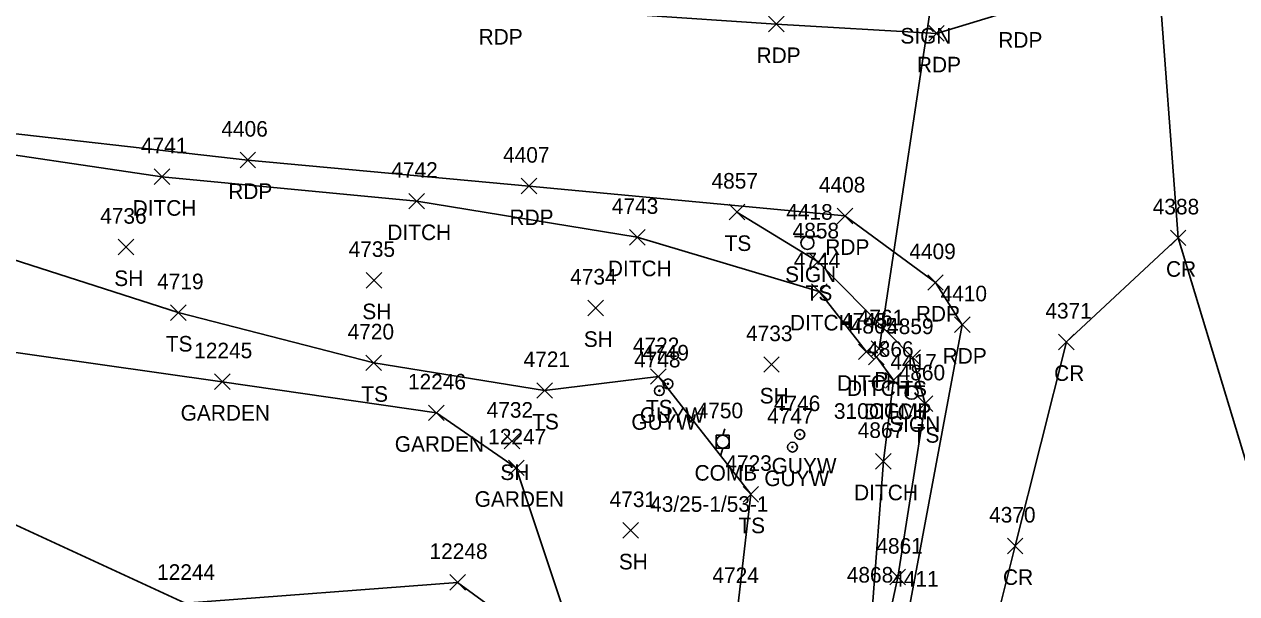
# Model space of a CAD drawing. Extents: x 1482574 to 1485769, y 580696 to 595649.
# Drawn here: x 1483403.4 to 1483558.8, y 583592.2 to 583665.3 of the extents above; entities that cross this region are included whole.
import ezdxf

# ---------------------------------------------------------------- set-up
doc = ezdxf.new("R2010")
doc.units = 0
for name, color, linetype in [('D_A', 7, 'Continuous'), ('D_C', 7, 'Continuous'), ('D_I', 7, 'Continuous'), ('D_TIC', 7, 'Continuous'), ('DCP', 7, 'Continuous'), ('DD', 7, 'Continuous'), ('L_A', 7, 'Continuous'), ('L_I', 7, 'Continuous'), ('L_TIC', 7, 'Continuous'), ('LAPB', 7, 'Continuous'), ('LELB', 7, 'Continuous'), ('P_A', 7, 'Continuous'), ('P_I', 7, 'Continuous'), ('P_TIC', 7, 'Continuous'), ('PET', 7, 'Continuous'), ('PRC', 7, 'Continuous'), ('S_A', 7, 'Continuous'), ('S_I', 7, 'Continuous'), ('SSGN', 7, 'Continuous'), ('U_A', 7, 'Continuous'), ('U_C', 7, 'Continuous'), ('U_I', 7, 'Continuous'), ('UP', 7, 'Continuous'), ('UPGW', 7, 'Continuous')]:
    doc.layers.add(name, color=color, linetype=linetype)

msp = doc.modelspace()

# ---------------------------------------------------------------- linework, layer by layer
at = {"layer": 'D_TIC'}
for points in [[(1483420.05, 583644.72), (1483422.05, 583646.72)], [(1483422.05, 583644.72), (1483420.05, 583646.72)], [(1483452.7, 583641.59), (1483454.7, 583643.59)], [(1483454.7, 583641.59), (1483452.7, 583643.59)], [(1483480.96, 583636.96), (1483482.96, 583638.96)], [(1483482.96, 583636.96), (1483480.96, 583638.96)], [(1483504.28, 583630), (1483506.28, 583632)], [(1483506.28, 583630), (1483504.28, 583632)], [(1483511.95, 583622.66), (1483513.95, 583624.66)], [(1483513.95, 583622.66), (1483511.95, 583624.66)], [(1483510.33, 583622.26), (1483512.33, 583624.26)], [(1483512.33, 583622.26), (1483510.33, 583624.26)], [(1483511.61, 583621.6), (1483513.61, 583623.6)], [(1483513.61, 583621.6), (1483511.61, 583623.6)], [(1483513.79, 583618.61), (1483515.79, 583620.61)], [(1483515.79, 583618.61), (1483513.79, 583620.61)], [(1483512.51, 583608.21), (1483514.51, 583610.21)], [(1483514.51, 583608.21), (1483512.51, 583610.21)]]:
    msp.add_lwpolyline(points, dxfattribs=at)
at = {"layer": 'DCP'}
msp.add_lwpolyline([(1483520.62, 583674.51), (1483512.95, 583623.66)], dxfattribs=at)
at = {"layer": 'DD'}
for points in [[(1483363.65, 583647.41), (1483379.49, 583650.79), (1483392.76, 583649.91), (1483421.05, 583645.72), (1483453.7, 583642.59), (1483481.96, 583637.96), (1483505.28, 583631), (1483511.33, 583623.26)], [(1483512.61, 583622.6), (1483514.79, 583619.61), (1483513.51, 583609.21), (1483512.11, 583590.65)]]:
    msp.add_lwpolyline(points, dxfattribs=at)
at = {"layer": 'L_TIC'}
for points in [[(1483493.74, 583640.2), (1483495.74, 583642.2)], [(1483495.74, 583640.2), (1483493.74, 583642.2)], [(1483415.45, 583635.7), (1483417.45, 583637.7)], [(1483417.45, 583635.7), (1483415.45, 583637.7)], [(1483504.13, 583633.81), (1483506.13, 583635.81)], [(1483506.13, 583633.81), (1483504.13, 583635.81)], [(1483447.23, 583631.44), (1483449.23, 583633.43)], [(1483449.23, 583631.44), (1483447.23, 583633.43)], [(1483422.13, 583627.29), (1483424.13, 583629.29)], [(1483424.13, 583627.29), (1483422.13, 583629.29)], [(1483475.62, 583627.89), (1483477.62, 583629.89)], [(1483477.62, 583627.89), (1483475.62, 583629.89)], [(1483447.19, 583620.85), (1483449.19, 583622.85)], [(1483449.19, 583620.85), (1483447.19, 583622.85)], [(1483516.25, 583621.53), (1483518.25, 583623.53)], [(1483518.25, 583621.53), (1483516.25, 583623.53)], [(1483498.16, 583620.63), (1483500.16, 583622.63)], [(1483500.16, 583620.63), (1483498.16, 583622.63)], [(1483427.78, 583618.43), (1483429.78, 583620.43)], [(1483429.78, 583618.43), (1483427.78, 583620.43)], [(1483483.66, 583619.09), (1483485.66, 583621.09)], [(1483485.66, 583619.09), (1483483.66, 583621.09)], [(1483469.08, 583617.3), (1483471.08, 583619.3)], [(1483471.08, 583617.3), (1483469.08, 583619.3)], [(1483517.85, 583615.6), (1483519.85, 583617.6)], [(1483519.85, 583615.6), (1483517.85, 583617.6)], [(1483455.21, 583614.43), (1483457.21, 583616.43)], [(1483457.21, 583614.43), (1483455.21, 583616.43)], [(1483464.92, 583610.81), (1483466.92, 583612.8)], [(1483466.92, 583610.81), (1483464.92, 583612.8)], [(1483465.45, 583607.37), (1483467.45, 583609.37)], [(1483467.45, 583607.37), (1483465.45, 583609.37)], [(1483495.51, 583603.98), (1483497.51, 583605.98)], [(1483497.51, 583603.98), (1483495.51, 583605.98)], [(1483480.11, 583599.35), (1483482.11, 583601.34)], [(1483482.11, 583599.35), (1483480.11, 583601.34)], [(1483514.34, 583593.36), (1483516.34, 583595.36)], [(1483516.34, 583593.36), (1483514.34, 583595.36)], [(1483457.93, 583592.68), (1483459.93, 583594.68)], [(1483459.93, 583592.68), (1483457.93, 583594.68)]]:
    msp.add_lwpolyline(points, dxfattribs=at)
at = {"layer": 'LAPB'}
msp.add_lwpolyline([(1483282.4, 583578.39), (1483283.47, 583588.15), (1483286.7, 583605.78), (1483289.8, 583624.64), (1483321.44, 583622.2), (1483367, 583615.82), (1483388.72, 583625.08), (1483428.78, 583619.43), (1483456.21, 583615.43), (1483466.45, 583608.37), (1483475.33, 583581.68)], dxfattribs=at)
at = {"layer": 'LELB'}
for points in [[(1482693.36, 583744.09), (1482726.2, 583730.25), (1482752.08, 583734.83), (1482783.99, 583736.05), (1482832.7, 583724.8), (1482871.74, 583713.41), (1482927.54, 583691.3), (1482963.28, 583665.68), (1482985.39, 583638.72), (1483019.29, 583636.93), (1483075.47, 583645.23), (1483111.09, 583648.77), (1483168.41, 583642.8), (1483210.26, 583617.48), (1483249.85, 583606.69), (1483286.7, 583605.78), (1483319.69, 583604.62), (1483362.38, 583602.89), (1483387.32, 583607.94), (1483424.01, 583591), (1483458.93, 583593.68), (1483475.33, 583581.68)], [(1483376.2, 583646.83), (1483397.16, 583636.64), (1483423.13, 583628.29), (1483448.19, 583621.85), (1483470.08, 583618.3), (1483484.66, 583620.09), (1483496.51, 583604.98), (1483494.85, 583590.59), (1483486.7, 583571.99), (1483482.44, 583553.2), (1483482.84, 583528.89)], [(1483494.74, 583641.2), (1483505.13, 583634.81), (1483517.25, 583622.53), (1483518.85, 583616.6), (1483515.34, 583594.36)], [(1483510.38, 583571.49), (1483515.34, 583594.36)]]:
    msp.add_lwpolyline(points, dxfattribs=at)
at = {"layer": 'P_TIC'}
for points in [[(1483498.77, 583664.31), (1483500.77, 583666.31)], [(1483500.77, 583664.31), (1483498.77, 583666.31)], [(1483519.31, 583663.11), (1483521.31, 583665.11)], [(1483521.31, 583663.11), (1483519.31, 583665.11)], [(1483431.05, 583646.87), (1483433.05, 583648.87)], [(1483433.05, 583646.87), (1483431.05, 583648.87)], [(1483467.1, 583643.53), (1483469.1, 583645.52)], [(1483469.1, 583643.53), (1483467.1, 583645.52)], [(1483507.58, 583639.7), (1483509.58, 583641.7)], [(1483509.58, 583639.7), (1483507.58, 583641.7)], [(1483550.28, 583636.89), (1483552.28, 583638.89)], [(1483552.28, 583636.89), (1483550.28, 583638.89)], [(1483519.18, 583631.15), (1483521.18, 583633.15)], [(1483521.18, 583631.15), (1483519.18, 583633.15)], [(1483522.61, 583625.74), (1483524.61, 583627.74)], [(1483524.61, 583625.74), (1483522.61, 583627.74)], [(1483535.95, 583623.53), (1483537.95, 583625.53)], [(1483537.95, 583623.53), (1483535.95, 583625.53)], [(1483529.39, 583597.35), (1483531.39, 583599.35)], [(1483531.39, 583597.35), (1483529.39, 583599.35)]]:
    msp.add_lwpolyline(points, dxfattribs=at)
at = {"layer": 'PET'}
for points in [[(1483366.75, 583680.51), (1483398.39, 583674.83), (1483429.12, 583670.98), (1483464.15, 583667.68), (1483499.77, 583665.31), (1483520.31, 583664.11), (1483530.74, 583667.28), (1483533.99, 583674.02), (1483537.43, 583706.71), (1483542.63, 583742.49), (1483548.55, 583777.29), (1483553.62, 583807.06)], [(1483359.39, 583657.75), (1483395.14, 583652.04), (1483432.05, 583647.87), (1483468.1, 583644.53), (1483508.57, 583640.7), (1483520.18, 583632.15), (1483523.61, 583626.74), (1483516.76, 583590.13)]]:
    msp.add_lwpolyline(points, dxfattribs=at)
at = {"layer": 'PRC'}
for points in [[(1483618.73, 583521.67), (1483605.12, 583536.57), (1483580.09, 583569.69), (1483562.2, 583601.73), (1483551.28, 583637.89), (1483548.66, 583672.74), (1483550.4, 583708.14), (1483555.34, 583744.78), (1483561.11, 583779.91), (1483565.84, 583808.31), (1483572.09, 583842.87), (1483580.82, 583892.49), (1483589.4, 583942.82)], [(1483551.28, 583637.89), (1483536.95, 583624.53)], [(1483530.39, 583598.35), (1483536.95, 583624.53)], [(1483522.82, 583568.08), (1483530.39, 583598.35)]]:
    msp.add_lwpolyline(points, dxfattribs=at)
at = {"layer": 'SSGN'}
for p, q in [((1483502.12, 583638.06), (1483505.46, 583638.06)), ((1483503.77, 583637.23), (1483503.77, 583637.23)), ((1483515.46, 583618.84), (1483518.8, 583618.84)), ((1483517.11, 583618), (1483517.11, 583618))]:
    msp.add_line(p, q, dxfattribs=at)
for centre in [(1483503.77, 583637.23), (1483517.11, 583618)]:
    msp.add_circle(centre, 0.833, dxfattribs=at)
at = {"layer": 'UP'}
for p, q in [((1483492.09, 583610.89), (1483492.09, 583612.56)), ((1483492.09, 583612.56), (1483493.75, 583612.56)), ((1483493.17, 583613.39), (1483492.92, 583612.56)), ((1483493.75, 583612.56), (1483493.75, 583610.89)), ((1483493.75, 583610.89), (1483492.09, 583610.89)), ((1483492.67, 583610.06), (1483492.92, 583610.89)), ((1483492.92, 583611.73), (1483492.92, 583611.73))]:
    msp.add_line(p, q, dxfattribs=at)
msp.add_circle((1483492.92, 583611.73), 0.833, dxfattribs=at)
at = {"layer": 'UPGW'}
for centre, radius in [((1483485.9, 583619.15), 0.625), ((1483484.8, 583618.26), 0.625), ((1483484.8, 583618.26), 0.0833), ((1483485.9, 583619.15), 0.0833), ((1483502.79, 583612.65), 0.625), ((1483502.79, 583612.65), 0.0833), ((1483501.85, 583611.03), 0.625), ((1483501.85, 583611.03), 0.0833)]:
    msp.add_circle(centre, radius, dxfattribs=at)

# ---------------------------------------------------------------- texts
at = {"layer": 'D_A'}
for s, p in [('DITCH', (1483417.29, 583640.72)), ('DITCH', (1483449.94, 583637.59)), ('DITCH', (1483478.19, 583632.96)), ('DITCH', (1483501.52, 583626)), ('DITCH', (1483507.57, 583618.26)), ('P', (1483512.33, 583618.66)), ('DITCH', (1483508.85, 583617.6)), ('DITCH', (1483511.02, 583614.61)), ('DITCH', (1483509.75, 583604.21))]:
    msp.add_text(s, height=2, dxfattribs=at).set_placement(p)
at = {"layer": 'D_C'}
msp.add_text('310CGMP', height=2, dxfattribs=at).set_placement((1483507.16, 583614.66))
at = {"layer": 'D_I'}
for s, p in [('4741', (1483418.36, 583648.72)), ('4742', (1483450.44, 583645.59)), ('4743', (1483478.7, 583640.96)), ('4744', (1483502.02, 583634)), ('4745', (1483508.07, 583626.26)), ('4865', (1483509.31, 583625.6)), ('4761', (1483510.21, 583626.66)), ('4866', (1483511.42, 583622.61)), ('4867', (1483510.21, 583612.21)), ('4868', (1483508.81, 583593.65))]:
    msp.add_text(s, height=2, dxfattribs=at).set_placement(p)
at = {"layer": 'L_A'}
for s, p in [('TS', (1483493.15, 583636.2)), ('SH', (1483414.93, 583631.7)), ('TS', (1483503.54, 583629.81)), ('SH', (1483446.72, 583627.44)), ('SH', (1483475.11, 583623.89)), ('TS', (1483421.54, 583623.29)), ('TS', (1483446.6, 583616.85)), ('SH', (1483497.65, 583616.63)), ('TS', (1483515.66, 583617.53)), ('TS', (1483483.07, 583615.09)), ('GARDEN', (1483423.44, 583614.43)), ('TS', (1483468.49, 583613.3)), ('TS', (1483517.26, 583611.6)), ('GARDEN', (1483450.88, 583610.43)), ('SH', (1483464.41, 583606.81)), ('GARDEN', (1483461.12, 583603.37)), ('TS', (1483494.92, 583599.98)), ('SH', (1483479.6, 583595.34))]:
    msp.add_text(s, height=2, dxfattribs=at).set_placement(p)
at = {"layer": 'L_I'}
for s, p in [('4857', (1483491.48, 583644.2)), ('4736', (1483413.13, 583639.7)), ('4858', (1483501.87, 583637.81)), ('4735', (1483444.97, 583635.44)), ('4734', (1483473.36, 583631.89)), ('4719', (1483420.43, 583631.29)), ('4859', (1483513.98, 583625.53)), ('4720', (1483444.84, 583624.85)), ('4733', (1483495.9, 583624.63)), ('12245', (1483425.18, 583622.43)), ('4722', (1483481.4, 583623.09)), ('4721', (1483467.39, 583621.3)), ('4860', (1483515.46, 583619.6)), ('12246', (1483452.57, 583618.43)), ('4732', (1483462.66, 583614.81)), ('12247', (1483462.86, 583611.37)), ('4723', (1483493.25, 583607.98)), ('4731', (1483478.42, 583603.34)), ('12248', (1483455.34, 583596.68)), ('4861', (1483512.6, 583597.36)), ('12244', (1483420.42, 583594)), ('4724', (1483491.59, 583593.59))]:
    msp.add_text(s, height=2, dxfattribs=at).set_placement(p)
at = {"layer": 'P_A'}
for s, p in [('RDP', (1483461.63, 583662.68)), ('RDP', (1483528.23, 583662.28)), ('RDP', (1483497.25, 583660.31)), ('RDP', (1483517.8, 583659.11)), ('RDP', (1483429.54, 583642.87)), ('RDP', (1483465.58, 583639.52)), ('RDP', (1483506.06, 583635.7)), ('CR', (1483549.72, 583632.89)), ('RDP', (1483517.66, 583627.15)), ('RDP', (1483521.1, 583621.74)), ('CR', (1483535.38, 583619.53)), ('CR', (1483528.83, 583593.35))]:
    msp.add_text(s, height=2, dxfattribs=at).set_placement(p)
at = {"layer": 'P_I'}
for s, p in [('4406', (1483428.66, 583650.87)), ('4407', (1483464.76, 583647.53)), ('4408', (1483505.24, 583643.7)), ('4388', (1483548.02, 583640.89)), ('4409', (1483516.83, 583635.15)), ('4410', (1483520.83, 583629.74)), ('4371', (1483534.26, 583627.53)), ('4370', (1483527.05, 583601.35)), ('4411', (1483514.64, 583593.13))]:
    msp.add_text(s, height=2, dxfattribs=at).set_placement(p)
at = {"layer": 'S_A'}
for p in [(1483515.68, 583662.81), (1483500.91, 583632.21), (1483514.25, 583612.98)]:
    msp.add_text('SIGN', height=2, dxfattribs=at).set_placement(p)
at = {"layer": 'S_I'}
for s, p in [('4418', (1483501.06, 583640.21)), ('4417', (1483514.4, 583620.98))]:
    msp.add_text(s, height=2, dxfattribs=at).set_placement(p)
at = {"layer": 'U_A'}
for s, p in [('GUYW', (1483481.2, 583613.26)), ('GUYW', (1483482.29, 583614.15)), ('GUYW', (1483499.18, 583607.65)), ('COMB', (1483489.3, 583606.73)), ('GUYW', (1483498.24, 583606.03))]:
    msp.add_text(s, height=2, dxfattribs=at).set_placement(p)
at = {"layer": 'U_C'}
msp.add_text('43/25-1/53-1', height=2, dxfattribs=at).set_placement((1483483.61, 583602.73))
at = {"layer": 'U_I'}
for s, p in [('4748', (1483481.55, 583621.26)), ('4749', (1483482.63, 583622.15)), ('4750', (1483489.57, 583614.73)), ('4746', (1483499.47, 583615.65)), ('4747', (1483498.59, 583614.03))]:
    msp.add_text(s, height=2, dxfattribs=at).set_placement(p)

doc.saveas('drawing.dxf')
